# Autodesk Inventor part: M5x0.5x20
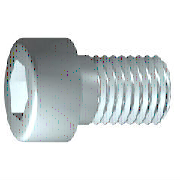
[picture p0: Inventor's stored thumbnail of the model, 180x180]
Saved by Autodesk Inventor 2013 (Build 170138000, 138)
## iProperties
IsCustomPart: 0
Company: 한국ATC센터
Created: 2009-02
Part Number: M5x0.5x20
Material: Steel, Mild
Description: 6각머리 태핑 나사
Document SubType Name: Modeling
Standard: KS B 1003
Designer: KYOUNG IL JANG
Standards Organization: KS
Language: ko-KR
Size Designation: M 5 x 20
Categories: <MemberInstance><Categories><Category DisplayName="조임쇠" InternalName="e4da775c-781d-43d5-af7c-5136215cf5a6" Mnemonic="FSTN"><Category DisplayName="볼트" InternalN
Density: 7.86 g/cm^3
Mass: 4.9629 g
Surface Area: 5.88237 cm^2
Volume: 0.631412 cm^3
Author: KYOUNG IL JANG
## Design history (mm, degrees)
sketch "스케치1"
  geometry: L1 (-1.167, 0)-(20, 0); L2 (20, 0)-(20, 2.5); L3 (20, 2.5)-(2, 2.5); L4 (2, 2.5)-(1.509, 2.5); L5 (1.509, 2.5)-(0, 2.5); L6 (0, 2.5)-(0, 4.25); L7 (0, 4.25)-(-5, 4.25); L8 (-5, 4.25)-(-5, 2.309); L9 (-5, 2.309)-(-2.5, 2.309); L10 (-2.5, 2.309)-(-1.167, 0); L11 (-10, 0)-(25, 0) reference; L12 (0, -0.85)-(0, 5.1) reference; L13 (2, 2.5)-(0, 2.5)
  constraints: 22 end point, 6 parallel, 2 collinear, 2 perpendicular, 1 horizontal, 1 point on line
  dimensions: "d1" = 18 distance from line of L3.end L2 (= GEL); "d2" = 0.49086 distance of L4.end L3.end (computed from GAL); "d3" = 5 distance between parallel lines of L8 L6 (= KOH); "d4" = 2.5 distance of L8.end L9.end (= INTI); "d5" = 60 deg angle of L10 L1; "d6" = 5 diameter of L3 L1 (= GD); "d7" = 5 diameter of L5 L1 (= BDM); "d8" = 4.6188 diameter of L9 L1 (= 1.1547 x SW); "d9" = 8.5 diameter of L7 L1 (= KOD); "d26" = 20 distance between parallel lines of L12 L2 (= NLG)
revolve "본체" sketch "스케치1" stored, may be unused: angle "d10" = 90 deg
sketch "스케치2"
  geometry: L1 (0, -5.95)-(0, 5.95) reference; L2 (-5.95, 0)-(5.95, 0) reference; L3 (2.309, 0)-(1.155, -2); L4 (1.155, -2)-(-1.155, -2); L5 (-1.155, -2)-(-2.309, 0); L6 (-2.309, 0)-(-1.155, 2); L7 (-1.155, 2)-(1.155, 2); L8 (1.155, 2)-(2.309, 0); 2 further points
  constraints: 12 end point, 1 coincident, 1 horizontal alignment, 1 point on line, 12 other
extrude "슬롯" join sketch "스케치2" stored distance "d11" = 10; taper "d12" = 0 deg
workplane "Work Plane1"
fillet "Fillet2" dims "d30" = 0.1 (= R)
body "Solid1"
fillet "모깎기1" dims "d17" = 0.5 (= RR)
feature "스레드" dims "d13" = 18 (= GEL), "d14" = 0
chamfer "모따기1" distance "d15" = 0.49076 (= -0.5 x SPD + 0.5 x GD); stored, may be unused: second distance "d16" = 0.49076 (= GUL), angle "d27" = 45 deg
other parameters: "GD" = 5 (= NND) [user parameter; used in 2 equation terms], "NLG" = 20 [user parameter; used in 1 equation term], "GEL" = 18 [user parameter; used in 2 equation terms], "KOD" = 8.5 [user parameter; used in 1 equation term], "KOH" = 5 [user parameter; used in 1 equation term], "INTI" = 2.5 [user parameter; used in 1 equation term], "GAL" = 0.49076 (= 0.61345 x PTC) [user parameter; used in 1 equation term], "GUL" = 0.49076 (= 0.61345 x PTC) [user parameter; used in 1 equation term], "BDM" = 5 (= NND) [user parameter; used in 1 equation term], "SW" = 4 [user parameter; used in 2 equation terms], "RR" = 0.5 [user parameter; used in 1 equation term], "SPD" = 4.01848 (= NND - 1.2269 x PTC) [user parameter; used in 1 equation term], "d19" = 0, "d28" = 0, "d29" = 0, "R" = 0.1 [user parameter; used in 1 equation term], "PHH" = 0.2 [user parameter], "GD1" = 4.01848 (= THREADDIA - 1.2269 x PTC) [user parameter], "THREADDIA" = 5 [user parameter; used in 1 equation term], "FAWI" = 45 deg [user parameter], "TPU" = 12.5 (computed from PTC) [user parameter], "PTC" = 0.8 [user parameter; used in 5 equation terms], "NND" = 5 [user parameter; used in 3 equation terms], "TOA" = 30 deg [user parameter], "E0" = 4.62 (= 1.155 x SW) [user parameter]
